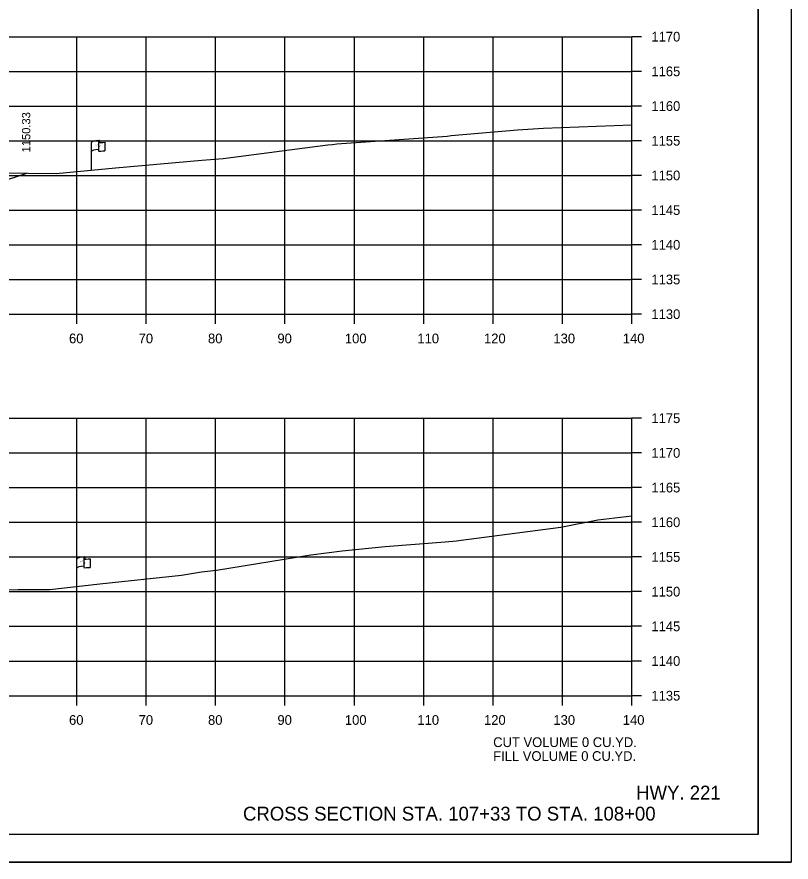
# Model space of a CAD drawing. Extents: x 1368971 to 1374497, y 378717 to 381839.
# Drawn here: x 1369694.3 to 1369805.9, y 378861.8 to 378983.7 of the extents above; entities that cross this region are included whole.
import ezdxf

# ---------------------------------------------------------------- set-up
doc = ezdxf.new("R2010")
doc.units = 0
for name, color, linetype in [('E_Existing ROW', 7, 'Continuous'), ('R_Axis', 7, 'Continuous'), ('R_Axis Annot', 7, 'Continuous'), ('R_Border', 7, 'Continuous'), ('R_Draft', 7, 'Continuous'), ('R_Exist Surface', 7, 'Continuous'), ('R_Fin Surface', 7, 'Continuous'), ('R_Grid', 7, 'Continuous'), ('R_No Plot', 7, 'Continuous'), ('R_Xsect Elev', 7, 'Continuous')]:
    doc.layers.add(name, color=color, linetype=linetype)

msp = doc.modelspace()

# ---------------------------------------------------------------- linework, layer by layer
at = {"layer": 'E_Existing ROW'}
for p, q in [((1369705.05, 378961.59), (1369705.05, 378965.54)), ((1369706.04, 378965.63), (1369706.04, 378965.62)), ((1369706.04, 378965.62), (1369706.04, 378964.39)), ((1369706.21, 378965.79), (1369706.21, 378965.55)), ((1369706.98, 378965.6), (1369706.98, 378964.36)), ((1369702.93, 378901.54), (1369702.93, 378905.49)), ((1369703.93, 378905.59), (1369703.93, 378905.57)), ((1369703.93, 378905.57), (1369703.93, 378904.35)), ((1369704.09, 378905.74), (1369704.09, 378905.5)), ((1369704.86, 378905.55), (1369704.86, 378904.31))]:
    msp.add_line(p, q, dxfattribs=at)
for centre, radius, start, end in [((1369706.12, 378965.64), 0.078, 88.6458, 274.2828), ((1369706.13, 378965.79), 0.0783, 263.0712, 93.9564), ((1369706.12, 378964.39), 0.0783, 180, 273.9564), ((1369704, 378905.59), 0.078, 88.6458, 274.2828), ((1369704.01, 378905.74), 0.0783, 263.0712, 93.9564), ((1369704, 378904.35), 0.0783, 180, 273.9564)]:
    msp.add_arc(centre, radius, start, end, dxfattribs=at)
for centre, major_axis, ratio, start_param, end_param in [((1369706.63, 378965.58), (-1.58, -0.04), 0.19887, 5.030368, 6.283185), ((1369707.34, 378965.7), (-1.23, -0.13), 0.052933, 0.159456, 1.268315), ((1369706.62, 378964.27), (-1.58, -0.04), 0.19887, 5.083035, 6.194897), ((1369707.34, 378964.46), (-1.23, -0.13), 0.052933, 0.159456, 1.268315), ((1369704.51, 378905.54), (-1.58, -0.04), 0.19887, 5.030368, 6.283185), ((1369705.22, 378905.65), (-1.23, -0.13), 0.052933, 0.159456, 1.268315), ((1369704.51, 378904.22), (-1.58, -0.04), 0.19887, 5.083035, 6.194897), ((1369705.22, 378904.41), (-1.23, -0.13), 0.052933, 0.159456, 1.268315)]:
    msp.add_ellipse(centre, major_axis=major_axis, ratio=ratio, start_param=start_param, end_param=end_param, dxfattribs=at)
at = {"layer": 'R_Axis'}
for p, q in [((1369782.93, 378940.81), (1369782.93, 378980.81)), ((1369784.33, 378980.81), (1369782.93, 378980.81)), ((1369784.33, 378975.81), (1369782.93, 378975.81)), ((1369784.33, 378970.81), (1369782.93, 378970.81)), ((1369784.33, 378965.81), (1369782.93, 378965.81)), ((1369784.33, 378960.81), (1369782.93, 378960.81)), ((1369784.33, 378955.81), (1369782.93, 378955.81)), ((1369784.33, 378950.81), (1369782.93, 378950.81)), ((1369784.33, 378945.81), (1369782.93, 378945.81)), ((1369502.93, 378940.81), (1369782.93, 378940.81)), ((1369702.93, 378939.41), (1369702.93, 378940.81)), ((1369712.93, 378939.41), (1369712.93, 378940.81)), ((1369722.93, 378939.41), (1369722.93, 378940.81)), ((1369732.93, 378939.41), (1369732.93, 378940.81)), ((1369742.93, 378939.41), (1369742.93, 378940.81)), ((1369752.93, 378939.41), (1369752.93, 378940.81)), ((1369762.93, 378939.41), (1369762.93, 378940.81)), ((1369772.93, 378939.41), (1369772.93, 378940.81)), ((1369782.93, 378939.41), (1369782.93, 378940.81)), ((1369784.33, 378940.81), (1369782.93, 378940.81)), ((1369782.93, 378885.81), (1369782.93, 378925.81)), ((1369784.33, 378925.81), (1369782.93, 378925.81)), ((1369784.33, 378920.81), (1369782.93, 378920.81)), ((1369784.33, 378915.81), (1369782.93, 378915.81)), ((1369784.33, 378910.81), (1369782.93, 378910.81)), ((1369784.33, 378905.81), (1369782.93, 378905.81)), ((1369784.33, 378900.81), (1369782.93, 378900.81)), ((1369784.33, 378895.81), (1369782.93, 378895.81)), ((1369784.33, 378890.81), (1369782.93, 378890.81)), ((1369502.93, 378885.81), (1369782.93, 378885.81)), ((1369702.93, 378884.41), (1369702.93, 378885.81)), ((1369712.93, 378884.41), (1369712.93, 378885.81)), ((1369722.93, 378884.41), (1369722.93, 378885.81)), ((1369732.93, 378884.41), (1369732.93, 378885.81)), ((1369742.93, 378884.41), (1369742.93, 378885.81)), ((1369752.93, 378884.41), (1369752.93, 378885.81)), ((1369762.93, 378884.41), (1369762.93, 378885.81)), ((1369772.93, 378884.41), (1369772.93, 378885.81)), ((1369782.93, 378884.41), (1369782.93, 378885.81)), ((1369784.33, 378885.81), (1369782.93, 378885.81))]:
    msp.add_line(p, q, dxfattribs=at)
at = {"layer": 'R_Border'}
for q in [(1369801.11, 379071.27), (1369484.93, 378865.81)]:
    msp.add_line((1369801.11, 378865.81), q, dxfattribs=at)
at = {"layer": 'R_Exist Surface'}
for points in [[(1369691.84, 378961.17), (1369699.98, 378961.1), (1369708.49, 378961.92), (1369720.93, 378963.02), (1369724.04, 378963.25), (1369739.12, 378965.22), (1369739.78, 378965.28), (1369740.42, 378965.34), (1369756.31, 378966.49), (1369756.88, 378966.55), (1369766.42, 378967.38), (1369770.18, 378967.62), (1369782.93, 378968.08)], [(1369690.26, 378900.99), (1369694.44, 378901.14), (1369699.06, 378901.1), (1369706.24, 378901.92), (1369718.04, 378903.18), (1369720.9, 378903.65), (1369723.05, 378903.91), (1369736.67, 378906.1), (1369741.16, 378906.68), (1369747.36, 378907.34), (1369756.01, 378907.97), (1369757.67, 378908.15), (1369758.3, 378908.25), (1369772.7, 378910.1), (1369778, 378911.15), (1369782.93, 378911.72)]]:
    msp.add_lwpolyline(points, dxfattribs=at)
at = {"layer": 'R_Fin Surface'}
msp.add_line((1369686.07, 378957.92), (1369695.73, 378961.13), dxfattribs=at)
at = {"layer": 'R_Grid'}
for p, q in [((1369502.93, 378980.81), (1369782.93, 378980.81)), ((1369702.93, 378940.81), (1369702.93, 378980.81)), ((1369712.93, 378940.81), (1369712.93, 378980.81)), ((1369722.93, 378940.81), (1369722.93, 378980.81)), ((1369732.93, 378940.81), (1369732.93, 378980.81)), ((1369742.93, 378940.81), (1369742.93, 378980.81)), ((1369752.93, 378940.81), (1369752.93, 378980.81)), ((1369762.93, 378940.81), (1369762.93, 378980.81)), ((1369772.93, 378940.81), (1369772.93, 378980.81)), ((1369782.93, 378940.81), (1369782.93, 378980.81)), ((1369502.93, 378975.81), (1369782.93, 378975.81)), ((1369502.93, 378970.81), (1369782.93, 378970.81)), ((1369502.93, 378965.81), (1369782.93, 378965.81)), ((1369502.93, 378960.81), (1369782.93, 378960.81)), ((1369502.93, 378955.81), (1369782.93, 378955.81)), ((1369502.93, 378950.81), (1369782.93, 378950.81)), ((1369502.93, 378945.81), (1369782.93, 378945.81)), ((1369502.93, 378940.81), (1369782.93, 378940.81)), ((1369502.93, 378925.81), (1369782.93, 378925.81)), ((1369702.93, 378885.81), (1369702.93, 378925.81)), ((1369712.93, 378885.81), (1369712.93, 378925.81)), ((1369722.93, 378885.81), (1369722.93, 378925.81)), ((1369732.93, 378885.81), (1369732.93, 378925.81)), ((1369742.93, 378885.81), (1369742.93, 378925.81)), ((1369752.93, 378885.81), (1369752.93, 378925.81)), ((1369762.93, 378885.81), (1369762.93, 378925.81)), ((1369772.93, 378885.81), (1369772.93, 378925.81)), ((1369782.93, 378885.81), (1369782.93, 378925.81)), ((1369502.93, 378920.81), (1369782.93, 378920.81)), ((1369502.93, 378915.81), (1369782.93, 378915.81)), ((1369502.93, 378910.81), (1369782.93, 378910.81)), ((1369502.93, 378905.81), (1369782.93, 378905.81)), ((1369502.93, 378900.81), (1369782.93, 378900.81)), ((1369502.93, 378895.81), (1369782.93, 378895.81)), ((1369502.93, 378890.81), (1369782.93, 378890.81)), ((1369502.93, 378885.81), (1369782.93, 378885.81))]:
    msp.add_line(p, q, dxfattribs=at)
at = {"layer": 'R_No Plot'}
msp.add_line((1369472.53, 378861.83), (1369805.86, 378861.83), dxfattribs=at)
for points in [[(1369472.52, 379075.16), (1369805.86, 379075.16), (1369805.86, 378861.82), (1369472.52, 378861.82)], [(1369718.85, 379071.27), (1369718.85, 379061.39), (1369754.58, 379061.39), (1369754.58, 379058.47), (1369777.78, 379058.47), (1369777.78, 379035.25), (1369801.11, 379035.25), (1369801.11, 378865.81), (1369484.93, 378865.81), (1369484.93, 379071.27)]]:
    msp.add_lwpolyline(points, close=True, dxfattribs=at)

# ---------------------------------------------------------------- texts
at = {"layer": 'E_Existing ROW'}
for s, height, rotation, p in [('R ', 0.2, 9.9884, (1369705.57, 378965.04)), (' O', 0.2, 9.9884, (1369705.71, 378965.09)), ('W', 0.2, 351.1788, (1369706.04, 378964.92)), ('DWB 11-9-07', 0.001, 90, (1369706.21, 378965.55)), ('DWB 11-9-07', 0.001, 5.0717, (1369706.97, 378964.36)), ('DWB 11-9-07', 0.001, 90, (1369705.05, 378961.59)), ('R ', 0.2, 9.9884, (1369703.45, 378904.99)), (' O', 0.2, 9.9884, (1369703.59, 378905.04)), ('DWB 11-9-07', 0.001, 90, (1369704.09, 378905.5)), ('W', 0.2, 351.1788, (1369703.92, 378904.87)), ('DWB 11-9-07', 0.001, 5.0717, (1369704.85, 378904.31)), ('DWB 11-9-07', 0.001, 90, (1369702.93, 378901.54))]:
    msp.add_text(s, height=height, rotation=rotation, dxfattribs=at).set_placement(p)
at = {"layer": 'R_Axis Annot'}
for s, p in [('1170', (1369785.73, 378980.11)), ('1165', (1369785.73, 378975.11)), ('1160', (1369785.73, 378970.11)), ('1155', (1369785.73, 378965.11)), ('1150', (1369785.73, 378960.11)), ('1145', (1369785.73, 378955.11)), ('1140', (1369785.73, 378950.11)), ('1135', (1369785.73, 378945.11)), ('1130', (1369785.73, 378940.11)), ('60', (1369701.81, 378936.61)), ('70', (1369711.84, 378936.61)), ('80', (1369721.84, 378936.61)), ('90', (1369731.84, 378936.61)), ('100', (1369741.56, 378936.61)), ('110', (1369752.01, 378936.61)), ('120', (1369761.61, 378936.61)), ('130', (1369771.61, 378936.61)), ('140', (1369781.61, 378936.61)), ('1175', (1369785.73, 378925.11)), ('1170', (1369785.73, 378920.11)), ('1165', (1369785.73, 378915.11)), ('1160', (1369785.73, 378910.11)), ('1155', (1369785.73, 378905.11)), ('1150', (1369785.73, 378900.11)), ('1145', (1369785.73, 378895.11)), ('1140', (1369785.73, 378890.11)), ('1135', (1369785.73, 378885.11)), ('60', (1369701.81, 378881.61)), ('70', (1369711.84, 378881.61)), ('80', (1369721.84, 378881.61)), ('90', (1369731.84, 378881.61)), ('100', (1369741.56, 378881.61)), ('110', (1369752.01, 378881.61)), ('120', (1369761.61, 378881.61)), ('130', (1369771.61, 378881.61)), ('140', (1369781.61, 378881.61)), ('CUT VOLUME 0 CU.YD.', (1369762.93, 378878.41)), ('FILL VOLUME 0 CU.YD.', (1369762.93, 378876.41))]:
    msp.add_text(s, height=1.4, dxfattribs=at).set_placement(p)
at = {"layer": 'R_Draft'}
for s, p in [('HWY. 221', (1369783.53, 378870.84)), ('CROSS SECTION STA. 107+33 TO STA. 108+00', (1369726.88, 378867.81))]:
    msp.add_text(s, height=2, dxfattribs=at).set_placement(p)
at = {"layer": 'R_Xsect Elev'}
msp.add_text('1150.33', height=1.2, rotation=90, dxfattribs=at).set_placement((1369696.23, 378964.13))

doc.saveas('drawing.dxf')
